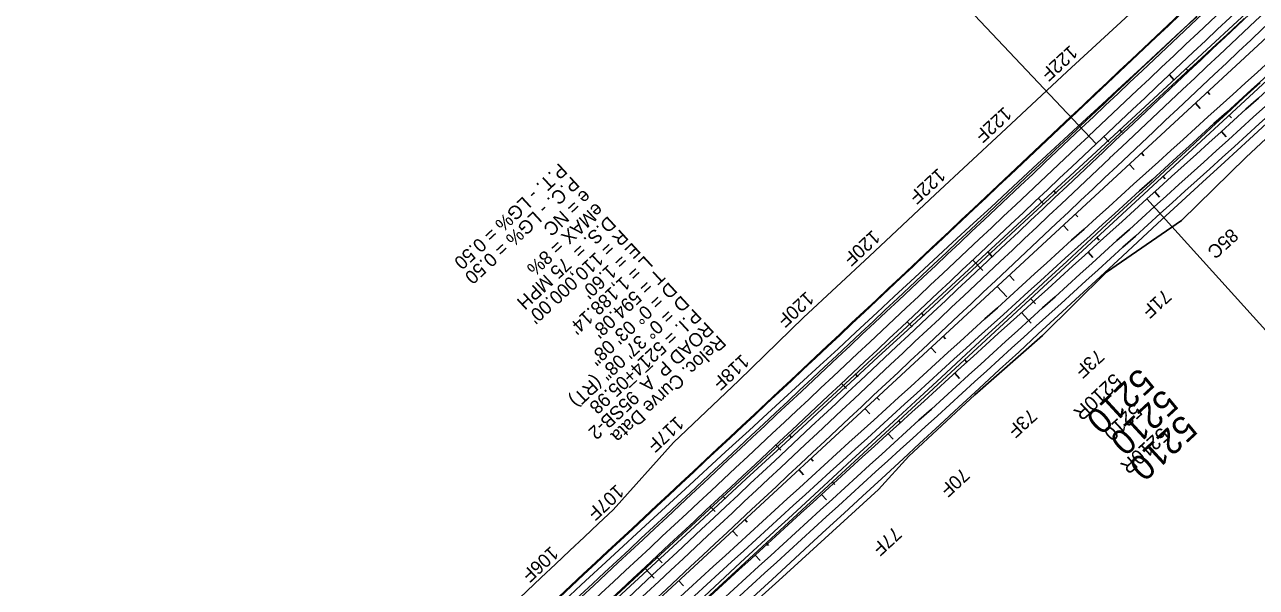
# Model space of a CAD drawing. Extents: x 2160876 to 2175990, y 601436 to 618246.
# Drawn here: x 2168336 to 2169705, y 610799 to 611423 of the extents above; entities that cross this region are included whole.
import ezdxf

# ---------------------------------------------------------------- set-up
doc = ezdxf.new("R2010")
doc.units = 0
for name, color, linetype in [('BNDY-ADJ', 7, 'Continuous'), ('BNDY-ADJ-TXT', 7, 'Continuous'), ('EX-UTIL-ELEC-TXT', 7, 'Continuous'), ('GN_Transparent 80', 7, 'Continuous'), ('RD_DTM_Major2', 7, 'Continuous'), ('RD_EX_BldgApp_Sign', 7, 'Continuous'), ('RD_EX_BldgApp_Steps', 7, 'Continuous'), ('RD_EX_DV_TX_Prop', 7, 'Continuous'), ('RD_EX_Fence_Gate', 7, 'Continuous'), ('RD_EX_RW', 7, 'Continuous'), ('RD_HC_Cl', 7, 'Continuous'), ('RD_HC_Data_Tic', 7, 'Continuous'), ('RD_HC_TX_Sta50', 7, 'Continuous'), ('RD_TX_RoadID', 7, 'Continuous')]:
    doc.layers.add(name, color=color, linetype=linetype)

msp = doc.modelspace()

# ---------------------------------------------------------------- linework, layer by layer
at = {"layer": 'BNDY-ADJ'}
msp.add_line((2172239.9, 613739.9), (2163704.8, 605858.6), dxfattribs=at)
at = {"layer": 'BNDY-ADJ-TXT'}
for centre, start, end in [((2245020.2, 531286.6), 132.719474, 133.338342), ((2095835.3, 692846.5), 312.100607, 312.719474), ((2094033.1, 691295.6), 312.719474, 313.338342), ((2243330.9, 529613.4), 132.100607, 132.719474)]:
    msp.add_arc(centre, 110000, start, end, dxfattribs=at)
at = {"layer": 'EX-UTIL-ELEC-TXT'}
for centre, radius, start, end in [((2245020.2, 531286.6), 110041.3, 132.719474, 133.338342), ((2245020.2, 531286.6), 110040.3, 132.719474, 133.338342), ((2245020.2, 531286.6), 110012, 132.719474, 133.338342), ((2245020.2, 531286.6), 110000, 132.719474, 133.338342), ((2245020.2, 531286.6), 109988, 132.719474, 133.338342), ((2095835.3, 692846.5), 109988, 312.100607, 312.719474), ((2095835.3, 692846.5), 110000, 312.100607, 312.719474), ((2095835.3, 692846.5), 110012, 312.100607, 312.719474), ((2094033.1, 691295.6), 109958.7, 312.719474, 313.338342), ((2094033.1, 691295.6), 109959.7, 312.719474, 313.338342), ((2094033.1, 691295.6), 109988, 312.719474, 313.338342), ((2094033.1, 691295.6), 110000, 312.719474, 313.338342), ((2094033.1, 691295.6), 110012, 312.719474, 313.338342), ((2243330.9, 529613.4), 110012, 132.100607, 132.719474), ((2243330.9, 529613.4), 110000, 132.100607, 132.719474), ((2243330.9, 529613.4), 109988, 132.100607, 132.719474)]:
    msp.add_arc(centre, radius, start, end, dxfattribs=at)
at = {"layer": 'GN_Transparent 80'}
for centre, radius, start, end in [((2245020.2, 531286.6), 110026.3, 132.719474, 133.338342), ((2245020.2, 531286.6), 110024, 132.719474, 133.338342), ((2094033.1, 691295.6), 109973.7, 312.719474, 313.338342), ((2094033.1, 691295.6), 109976, 312.719474, 313.338342)]:
    msp.add_arc(centre, radius, start, end, dxfattribs=at)
at = {"layer": 'RD_DTM_Major2'}
for p, q in [((2169637, 611336.4), (2169642.5, 611330.5)), ((2169563.6, 611268.6), (2169569, 611262.7)), ((2169490.1, 611200.7), (2169495.5, 611194.8)), ((2169416.6, 611132.9), (2169427.5, 611121.1)), ((2169343.2, 611065), (2169348.6, 611059.2)), ((2169269.7, 610997.2), (2169275.1, 610991.3)), ((2169196.2, 610929.4), (2169201.7, 610923.5)), ((2169122.8, 610861.5), (2169128.2, 610855.6))]:
    msp.add_line(p, q, dxfattribs=at)
at = {"layer": 'RD_EX_BldgApp_Sign'}
for centre, radius, start, end in [((2245020.2, 531286.6), 109966, 132.719474, 133.338342), ((2094033.1, 691295.6), 110034, 312.719474, 313.338342)]:
    msp.add_arc(centre, radius, start, end, dxfattribs=at)
at = {"layer": 'RD_EX_BldgApp_Steps'}
for p, q in [((2172672.7, 614139.6), (2163700.6, 605854.7)), ((2169773.5, 611510.3), (2165657.1, 607709.2)), ((2169821.3, 611458.6), (2165682.4, 607636.8)), ((2169626.6, 611374.6), (2169629.3, 611371.7)), ((2169650.5, 611348.8), (2169653.2, 611345.9)), ((2169674.3, 611323), (2169677, 611320)), ((2169553.1, 611306.8), (2169555.8, 611303.8)), ((2169577, 611281), (2169579.7, 611278)), ((2169600.9, 611255.1), (2169603.6, 611252.2)), ((2169479.7, 611238.9), (2169482.4, 611236)), ((2169503.5, 611213.1), (2169506.2, 611210.2)), ((2169527.4, 611187.3), (2169530.1, 611184.3)), ((2169406.2, 611171.1), (2169411.6, 611165.2)), ((2169430.1, 611145.3), (2169435.5, 611139.4)), ((2169453.9, 611119.4), (2169459.3, 611113.6)), ((2169332.7, 611103.3), (2169335.4, 611100.3)), ((2169356.6, 611077.4), (2169359.3, 611074.5)), ((2169380.4, 611051.6), (2169383.2, 611048.7)), ((2169259.3, 611035.4), (2169262, 611032.5)), ((2169283.1, 611009.6), (2169285.8, 611006.6)), ((2169307, 610983.8), (2169309.7, 610980.8)), ((2169185.8, 610967.6), (2169188.5, 610964.6)), ((2169209.7, 610941.7), (2169212.4, 610938.8)), ((2169233.5, 610915.9), (2169236.2, 610913)), ((2169112.3, 610899.7), (2169115, 610896.8)), ((2169136.2, 610873.9), (2169138.9, 610871)), ((2169160, 610848.1), (2169162.8, 610845.1)), ((2169038.9, 610831.9), (2169044.3, 610826)), ((2169062.7, 610806.1), (2169068.1, 610800.2))]:
    msp.add_line(p, q, dxfattribs=at)
at = {"layer": 'RD_EX_Fence_Gate'}
for p, q in [((2169568.4, 611439.1), (2169494.5, 611371.4)), ((2169494.5, 611371.4), (2169421.2, 611303.1)), ((2169421.2, 611303.1), (2169347.9, 611234.9)), ((2169347.9, 611234.9), (2169275, 611166.3)), ((2169275, 611166.3), (2169201.5, 611098.2)), ((2169201.5, 611098.2), (2169129.7, 611028.4)), ((2169129.7, 611028.4), (2169057, 610959.4)), ((2169057, 610959.4), (2168989.9, 610884.6))]:
    msp.add_line(p, q, dxfattribs=at)
msp.add_lwpolyline([(2169947.4, 611516.2), (2169906.8, 611486.5), (2169832.2, 611419.8), (2169766.1, 611344.1), (2169692.9, 611276), (2169621.4, 611206), (2169538.3, 611148.5), (2169467, 611078.3), (2169391.8, 611012.4), (2169318.6, 610944.2), (2169284.7, 610907.2), (2169174, 610806.1), (2169099.5, 610739.3), (2169025.5, 610672), (2168948.7, 610607.8), (2168874.4, 610540.9), (2168798.4, 610475.8), (2168741.5, 610390), (2168667.6, 610322.7), (2168592.4, 610252), (2168544.5, 610187.1)], dxfattribs=at)
msp.add_arc((2219097.5, 557675.8), 73088.7, 133.280708, 133.830736, dxfattribs=at)
at = {"layer": 'RD_EX_RW'}
for p, q in [((2169568.4, 611439.1), (2169494.5, 611371.4)), ((2169494.5, 611371.4), (2169421.2, 611303.1)), ((2169421.2, 611303.1), (2169347.9, 611234.9)), ((2169347.9, 611234.9), (2169275, 611166.3)), ((2169275, 611166.3), (2169201.5, 611098.2)), ((2169201.5, 611098.2), (2169129.7, 611028.4)), ((2169129.7, 611028.4), (2169057, 610959.4)), ((2169057, 610959.4), (2168989.9, 610884.6))]:
    msp.add_line(p, q, dxfattribs=at)
for points in [[(2168922.8, 610772), (2168954.6, 610801.5), (2168986.7, 610831.2), (2169030.7, 610871.8), (2169070, 610907.7), (2169114.8, 610949.2), (2169130.1, 610963), (2169141, 610972.9), (2169156.8, 610987.3), (2169175.3, 611004.3), (2169196.9, 611024.2), (2169219.6, 611045.1), (2169240, 611063.6), (2169259.6, 611082), (2169283.2, 611103.8), (2169302.2, 611121.8), (2169325.4, 611142.9), (2169345.8, 611161.8), (2169367.2, 611181.7), (2169390.3, 611203), (2169409.9, 611221), (2169428.7, 611238.2), (2169451.2, 611259.2), (2169471.7, 611278.2), (2169490.9, 611296), (2169511.7, 611315.4), (2169533.3, 611335.3), (2169555.2, 611355.6), (2169576.6, 611375.3), (2169598.6, 611395.4), (2169620.4, 611415.8), (2169638.6, 611432.1)], [(2169691.4, 611430.2), (2169672.4, 611412.6), (2169656.2, 611397.8), (2169643.9, 611386.4), (2169626.2, 611370.1), (2169597.1, 611343.3), (2169568.7, 611316.9), (2169543.2, 611293.5), (2169512.7, 611265), (2169484.2, 611239.1), (2169456.9, 611213.8), (2169432.1, 611190.8), (2169404.3, 611165), (2169373.8, 611136.7), (2169346.9, 611111.8), (2169317.6, 611084.8), (2169284.4, 611054.5), (2169258.9, 611030.8), (2169227.7, 611002.1), (2169200.3, 610976.6), (2169172.3, 610950.8), (2169137.9, 610919.1), (2169106.6, 610890.2), (2169075.5, 610861.4), (2168985.1, 610778.3)], [(2168965.7, 610622), (2169025.5, 610672), (2169099.5, 610739.3), (2169174, 610806.1), (2169284.7, 610907.2), (2169318.6, 610944.2), (2169391.8, 611012.4), (2169467, 611078.3), (2169538.3, 611148.5), (2169621.4, 611206), (2169692.9, 611276), (2169766.1, 611344.1), (2169824.9, 611411.5)], [(2169085.5, 610783.5), (2169131.6, 610826.1), (2169173.5, 610864.7), (2169184.4, 610874.9), (2169213.7, 610901.9), (2169239.2, 610925.4), (2169255.3, 610940.2), (2169282, 610964.8), (2169306.7, 610987.5), (2169330.7, 611009.7), (2169354.6, 611031.7), (2169377.1, 611052.6), (2169402.7, 611076.3), (2169427.5, 611099), (2169451.4, 611121.3), (2169473.1, 611141.1), (2169494.1, 611160.6), (2169516.3, 611181.1), (2169538.4, 611201.7), (2169561.7, 611223.1), (2169586.6, 611246.1), (2169607.9, 611265.8), (2169630.4, 611286.4), (2169655, 611309.2), (2169676.8, 611329.3), (2169690.7, 611342.5), (2169709, 611358.8)], [(2169720.8, 611318.2), (2169697, 611296.4), (2169669.7, 611271.2), (2169645.1, 611248.6), (2169622, 611227.4), (2169599.9, 611207.1), (2169578.6, 611187.4), (2169556, 611166.4), (2169531.2, 611143.6), (2169508.4, 611122.5), (2169484.6, 611100.7), (2169462.4, 611080.1), (2169440.7, 611060), (2169419.5, 611040.6), (2169396.9, 611019.6), (2169374.1, 610998.6), (2169353.1, 610979.2), (2169330.6, 610958.5), (2169312.1, 610941.5), (2169288.4, 610919.5), (2169267, 610899.8), (2169246.6, 610880.9), (2169226.7, 610862.8), (2169208.3, 610845.8), (2169197.5, 610835.8), (2169166.6, 610807.4), (2169115.3, 610760.4)]]:
    msp.add_lwpolyline(points, dxfattribs=at)
msp.add_arc((2219097.5, 557675.8), 73088.7, 133.280708, 133.830736, dxfattribs=at)
at = {"layer": 'RD_HC_Cl'}
for p, q in [((2169608.1, 611367.8), (2169613.6, 611362)), ((2169666.1, 611305), (2169671.4, 611299.1)), ((2169535.3, 611299.2), (2169540.8, 611293.4)), ((2169591.9, 611237.9), (2169597.3, 611232)), ((2169462.5, 611230.6), (2169468, 611224.8)), ((2169517.7, 611170.9), (2169523.1, 611164.9)), ((2169389.7, 611162.1), (2169400.7, 611150.4)), ((2169443.6, 611103.7), (2169454.4, 611091.9)), ((2169316.8, 611093.6), (2169322.3, 611087.8)), ((2169369.6, 611036.5), (2169374.9, 611030.6)), ((2169243.9, 611025.2), (2169249.4, 611019.4)), ((2169295.6, 610969.3), (2169301, 610963.3)), ((2169170.9, 610956.9), (2169176.4, 610951)), ((2169221.6, 610901.9), (2169227, 610896)), ((2169097.8, 610888.6), (2169103.3, 610882.7)), ((2169147.8, 610834.5), (2169153.2, 610828.6)), ((2169024.7, 610820.4), (2169035.6, 610808.7))]:
    msp.add_line(p, q, dxfattribs=at)
at = {"layer": 'RD_HC_TX_Sta50'}
for p, q in [((2169268.2, 611565), (2169526.6, 611291.1)), ((2169883, 610898), (2169583.1, 611230))]:
    msp.add_line(p, q, dxfattribs=at)
at = {"layer": 'RD_TX_RoadID'}
for centre, radius, start, end in [((2245020.2, 531286.6), 110024, 132.719474, 133.338342), ((2245020.2, 531286.6), 109978, 132.719474, 133.338342), ((2095835.3, 692846.5), 109978, 312.100607, 312.719474), ((2095835.3, 692846.5), 110022, 312.100607, 312.719474), ((2094033.1, 691295.6), 109976, 312.719474, 313.338342), ((2094033.1, 691295.6), 110022, 312.719474, 313.338342), ((2243330.9, 529613.4), 110022, 132.100607, 132.719474), ((2243330.9, 529613.4), 109978, 132.100607, 132.719474)]:
    msp.add_arc(centre, radius, start, end, dxfattribs=at)

# ---------------------------------------------------------------- texts
at = {"layer": 'RD_EX_BldgApp_Steps'}
for p in [(2169574.8, 611043.7), (2169601.2, 611020.2), (2169622.5, 610992)]:
    msp.add_text('5210', height=28, rotation=222.7195, dxfattribs=at).set_placement(p)
at = {"layer": 'RD_EX_DV_TX_Prop'}
msp.add_text('5210', height=16, rotation=222.7195, dxfattribs=at).set_placement((2169568.7, 611003.8))
at = {"layer": 'RD_EX_Fence_Gate'}
for s, rotation, p in [('122F', 222.2809, (2169497.8, 611401.5)), ('122F', 222.3594, (2169424.5, 611333.2)), ('122F', 222.4379, (2169351.1, 611265)), ('120F', 222.5164, (2169278.2, 611196.3)), ('85C', 222.2809, (2169676.3, 611198.2)), ('120F', 222.5949, (2169204.7, 611128.2)), ('71F', 222.3594, (2169601.8, 611130.6)), ('118F', 222.6733, (2169132.8, 611058.4)), ('73F', 222.4379, (2169527.3, 611064.1)), ('117F', 222.7518, (2169060.1, 610989.5)), ('73F', 222.5164, (2169452.6, 610998)), ('70F', 222.5949, (2169377.5, 610932.2)), ('107F', 222.8303, (2168993.6, 610913.9)), ('77F', 222.6733, (2169302, 610866.9)), ('106F', 222.9088, (2168920.7, 610845.2))]:
    msp.add_text(s, height=15, rotation=rotation, dxfattribs=at).set_placement(p)
at = {"layer": 'RD_HC_Data_Tic'}
for rotation, p in [(223.2404, (2169546.1, 611037.4)), (222.1986, (2169598.9, 610977.3))]:
    msp.add_text('5210R', height=16, rotation=rotation, dxfattribs=at).set_placement(p)
at = {"layer": 'RD_HC_TX_Sta50'}
for s, p in [('P.T. - LG% = 0.50', (2168930.3, 611270.6)), ('P.C. - LG% = 0.50', (2168943.8, 611255.9)), ('e = NC', (2168957.4, 611241.2)), ('eMAX = 8%', (2168971, 611226.5)), ('D.S. =  75 MPH', (2168984.5, 611211.8)), ("R = 110,000.00'", (2168998.1, 611197.1)), ("E = 1.60'", (2169011.7, 611182.4)), ("L = 1,188.14'", (2169025.2, 611167.8)), ("T = 594.08'", (2169038.8, 611153.1)), ('D = 0° 03\' 08"', (2169052.4, 611138.4)), ('D', (2169066, 611123.7)), ('    = 0° 37\' 08" (RT)', (2169066, 611123.7)), ('P.I. = 5214+05.98', (2169079.5, 611109)), ('ROAD P_A_95SB-2', (2169093.1, 611094.3)), ('Reloc. Curve Data', (2169106.7, 611079.6))]:
    msp.add_text(s, height=15, rotation=222.7195, dxfattribs=at).set_placement(p)

doc.saveas('drawing.dxf')
